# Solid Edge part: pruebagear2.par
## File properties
Author: there
Template: SEER_ExtSpurGear.par
Last saved by: there
Revision: 2
Application: Solid Edge
Density: 7833.000 kg/m^3
Accuracy: 0.990
SEER_Parameters: SEERSG2#ER#3#ER#0.349065850398866#ER#0.003#ER#0.05#ER#0#ER#0.0002#ER#0#ER#1#ER#1.2#ER#0.8#ER#10000#ER#1#ER#1#ER#30#ER#90#ER#0.01#ER#0.02#ER#0.03#ER#0.03#ER#0#ER#0#ER#1000#ER#1000#ER#104.71975511966#ER#104.71975511966#ER#9.54#ER#9.54#ER#0.92#ER#1#ER#1#ER#1#ER#1#ER#0#ER#0#ER#1#ER#0#ER#0#ER#1#ER#0#ER#0#ER#0.08#ER#0.08#ER#0.008#ER#0.008#ER#0.025#ER#0.025#ER#0#ER#1140#ER#605#ER#0#ER#1140#ER#390#ER#12#ER#SweptProtrusion_1#ER#Pattern_1#ER#SweptProtrusion_1#ER#Pattern_1#ER##ER#C:\Users\there\Documents\CarroInertia\pruebagear1.par#ER#0#ER#0#ER#ExtrudedProtrusion_4#ER#ExtrudedCutout_5#ER#ExtrudedProtrusion_4#ER#ExtrudedCutout_5#ER#0#ER#1#ER#0#ER#0#ER#False#ER#0
Username: there
Material: Steel
Face Style: Steel
Fill Style: ANSI32(Steel)
Virtual Style: Machined steel
Coef. of Thermal Exp: 1.3e-05
Thermal Conductivity: 32.0
Specific Heat: 481.0
Modulus of Elasticity: 199947953000.0
Poission's Ratio: 0.29
Yield Stress: 262000766.0
Ultimate Stress: 358527364.0
Elongation: 0.0
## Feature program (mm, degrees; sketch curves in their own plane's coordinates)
sketch for "unnamed Protrusion 1" plane through (0, 0, 0) normal (0, 0, 1) x-axis (1, 0, 0)
  circle centre (0, 0) radius 35.848
extrude "unnamed Protrusion 1" add finite 30 along +normal
sketch for "unnamed Cutout 1" plane through (0, 0, 30) normal (0, 0, 1) x-axis (0, 1, 0)
extrude "unnamed Cutout 1" cut through along -normal
swept protrusion "ProtrusiónPorBarrido_1"
swept protrusion "unnamed SweptProtrusion 1"
swept protrusion "unnamed SweptProtrusion 2"
swept protrusion "unnamed SweptProtrusion 3"
swept protrusion "unnamed SweptProtrusion 4"
swept protrusion "unnamed SweptProtrusion 5"
swept protrusion "unnamed SweptProtrusion 6"
swept protrusion "unnamed SweptProtrusion 7"
swept protrusion "unnamed SweptProtrusion 8"
swept protrusion "unnamed SweptProtrusion 9"
swept protrusion "unnamed SweptProtrusion 10"
swept protrusion "unnamed SweptProtrusion 11"
swept protrusion "unnamed SweptProtrusion 12"
swept protrusion "unnamed SweptProtrusion 13"
swept protrusion "unnamed SweptProtrusion 14"
swept protrusion "unnamed SweptProtrusion 15"
swept protrusion "unnamed SweptProtrusion 16"
swept protrusion "unnamed SweptProtrusion 17"
swept protrusion "unnamed SweptProtrusion 18"
swept protrusion "unnamed SweptProtrusion 19"
swept protrusion "unnamed SweptProtrusion 20"
swept protrusion "unnamed SweptProtrusion 21"
swept protrusion "unnamed SweptProtrusion 22"
swept protrusion "unnamed SweptProtrusion 23"
swept protrusion "unnamed SweptProtrusion 24"
swept protrusion "unnamed SweptProtrusion 25"
swept protrusion "unnamed SweptProtrusion 26"
swept protrusion "unnamed SweptProtrusion 27"
swept protrusion "unnamed SweptProtrusion 28"
swept protrusion "unnamed SweptProtrusion 29"
swept protrusion "unnamed SweptProtrusion 30"
swept protrusion "unnamed SweptProtrusion 31"
swept protrusion "unnamed SweptProtrusion 32"
swept protrusion "unnamed SweptProtrusion 33"
swept protrusion "unnamed SweptProtrusion 34"
swept protrusion "unnamed SweptProtrusion 35"
swept protrusion "unnamed SweptProtrusion 36"
swept protrusion "unnamed SweptProtrusion 37"
swept protrusion "unnamed SweptProtrusion 38"
swept protrusion "unnamed SweptProtrusion 39"
swept protrusion "unnamed SweptProtrusion 40"
swept protrusion "unnamed SweptProtrusion 41"
swept protrusion "unnamed SweptProtrusion 42"
swept protrusion "unnamed SweptProtrusion 43"
swept protrusion "unnamed SweptProtrusion 44"
swept protrusion "unnamed SweptProtrusion 45"
swept protrusion "unnamed SweptProtrusion 46"
swept protrusion "unnamed SweptProtrusion 47"
swept protrusion "unnamed SweptProtrusion 48"
swept protrusion "unnamed SweptProtrusion 49"
swept protrusion "unnamed SweptProtrusion 50"
swept protrusion "unnamed SweptProtrusion 51"
swept protrusion "unnamed SweptProtrusion 52"
swept protrusion "unnamed SweptProtrusion 53"
swept protrusion "unnamed SweptProtrusion 54"
swept protrusion "unnamed SweptProtrusion 55"
swept protrusion "unnamed SweptProtrusion 56"
swept protrusion "unnamed SweptProtrusion 57"
swept protrusion "unnamed SweptProtrusion 58"
swept protrusion "unnamed SweptProtrusion 59"
base feature "unnamed BaseFeature 1"
sketch for "ProtrusiónExtruida_4" plane through (0, 0, 0) normal (0, 0, 1) x-axis (1, 0, 0)
  circle centre (0, 0) radius 37.5
extrude "ProtrusiónExtruida_4" add finite 30 along +normal
sketch for "VaciadoExtruido_5" plane through (0, 0, 0) normal (0, 0, 1) x-axis (1, 0, 0)
  circle centre (0, 0) radius 37.5
extrude "VaciadoExtruido_5" cut finite 30 along +normal
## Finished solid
Body 1: sheet body, 1 face, 2 edges, 0 vertices.
  Faces by surface: cylinder 1
  Edges by curve: circle 2
Body 2: solid body, 243 faces, 722 edges, 480 vertices.
  Faces by surface: spline 180, cylinder 61, plane 2
  Edges by curve: spline 360, circle 242, intersection 118, line 2
Bounding box of the edges (mm; curved faces can reach further): 77.321 x 77.321 x 30.000, from (-38.6605, -38.6605, 0) to (38.6605, 38.6605, 30).
Cylindrical faces by radius (mm): R10 x1, R35.848 x60, R37.5 x1
Planar faces by outward normal: +z 1, -z 1
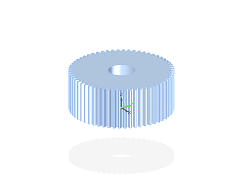
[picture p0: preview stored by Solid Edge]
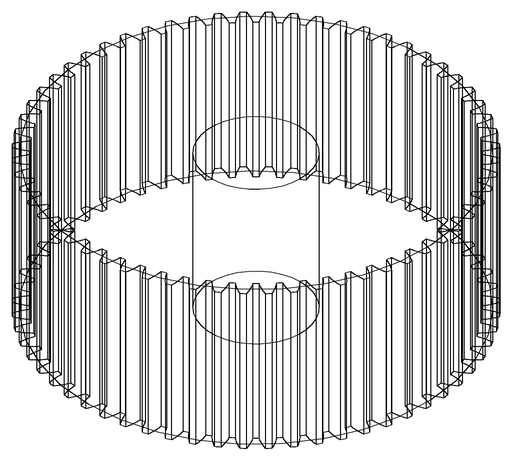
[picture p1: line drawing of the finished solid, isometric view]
